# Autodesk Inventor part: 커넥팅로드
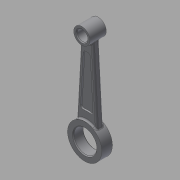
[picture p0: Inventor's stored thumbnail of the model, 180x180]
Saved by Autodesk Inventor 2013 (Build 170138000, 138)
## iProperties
Created: 2016-11
Part Number: 커넥팅로드
Material: 일반
Document SubType Name: Modeling
Designer: mduedu
Density: 1 g/cm^3
Author: mduedu
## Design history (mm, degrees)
sketch "스케치1" dims "d0" = 42, "d3" = 20
  geometry: L1 (0, 0)-(0, 114); L2 (-7.5, 107.386)-(-12.5, 16.875); L3 (7.5, 107.386)-(12.5, 16.875); C1 r 14 at (0, 0); C2 r 6.5 at (0, 114); 3 further points
  constraints: 6 end point, 4 coincident, 2 centre point, 2 symmetric about line, 1 vertical, 6 other
  dimensions: "d1" = 28 diameter of C1; "d2" = 13 diameter of C2; "d4" = 114 distance of L1.start L1.end; "d6" = 12.5 distance from line of L1 L2.end; "d7" = 7.5 distance from line of L1 L2.start
extrude "돌출1" new body sketch "스케치1" stored distance "d8" = 13; taper "d9" = 0 deg
extrude "돌출2" join sketch "스케치1" stored distance "d10" = 20; taper "d11" = 0 deg
sketch "스케치2"
  geometry: L1 (-7.5, 107.386)-(-12.5, 16.875) reference; L2 (7.5, 107.386)-(12.5, 16.875) reference; A1 r 10 centre (0, 114) between (-7.5, 107.386) and (7.5, 107.386) reference; A2 r 21 centre (0, 0) between (-12.5, 16.875) and (12.5, 16.875) reference; 1 further point
extrude "돌출3" join sketch "스케치2" stored distance "d12" = 8; taper "d13" = 0 deg
sketch "스케치3"
  geometry: L1 (-7.5, 107.386)-(-12.5, 16.875) reference; L2 (7.5, 107.386)-(12.5, 16.875) reference; L3 (-4.209, 94.448)-(-7.768, 30.011); L4 (4.209, 94.448)-(7.768, 30.011); L5 (0, 94)-(0, 31); A1 r 10 centre (0, 114) between (-7.5, 107.386) and (7.5, 107.386) reference; A2 r 21 centre (0, 0) between (-12.5, 16.875) and (12.5, 16.875) reference; A3 r 20 centre (0, 114) between (-4.209, 94.448) and (4.209, 94.448); A4 r 31 centre (0, 0) between (7.768, 30.011) and (-7.768, 30.011); 1 further point
  constraints: 6 end point, 6 point on circle, 2 centre point, 2 parallel, 1 symmetric about line, 1 vertical alignment
  dimensions: "d18" = 10 radial gap between concentric circles of A3 A1; "d19" = 10 radial gap between concentric circles of A2 A4; "d20" = 4 distance between parallel lines of L3 L1
extrude "돌출4" cut sketch "스케치3" distance "d21" = 2; taper "d22" = 0 deg
fillet "모깎기1" dims "d23" = 3
fillet "모깎기2" dims "d24" = 2
fillet "모깎기3" dims "d25" = 2
chamfer "모따기1" distance "d26" = 1; stored, may be unused: second distance "d27" = 2, angle "d28" = 45 deg
node "솔리드1"
mirror "대칭1"
other parameters: "d16" = 4, "d17" = 4
